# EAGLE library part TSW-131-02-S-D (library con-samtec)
THROUGH-HOLE .025" SQ POST HEADER Source: Samtec TSW.pdf
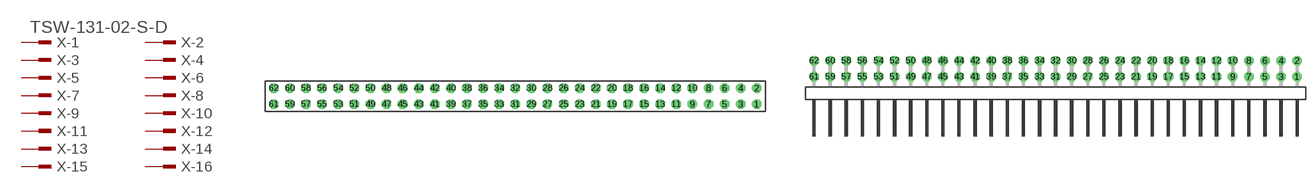
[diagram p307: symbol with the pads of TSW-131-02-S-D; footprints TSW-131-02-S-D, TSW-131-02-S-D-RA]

Designator prefix X; gates -1=MPINV -2=MPIN -3=MPIN -4=MPIN -5=MPIN -6=MPIN -7=MPIN -8=MPIN -9=MPIN -10=MPIN -11=MPIN -12=MPIN -13=MPIN -14=MPIN -15=MPIN -16=MPIN -17=MPIN -18=MPIN -19=MPIN -20=MPIN -21=MPIN -22=MPIN -23=MPIN -24=MPIN -25=MPIN -26=MPIN -27=MPIN -28=MPIN -29=MPIN -30=MPIN -31=MPIN -32=MPIN -33=MPIN -34=MPIN -35=MPIN -36=MPIN -37=MPIN -38=MPIN -39=MPIN -40=MPIN -41=MPIN -42=MPIN -43=MPIN -44=MPIN -45=MPIN -46=MPIN -47=MPIN -48=MPIN -49=MPIN -50=MPIN -51=MPIN -52=MPIN -53=MPIN -54=MPIN -55=MPIN -56=MPIN -57=MPIN -58=MPIN -59=MPIN -60=MPIN -61=MPIN -62=MPIN

## TSW-131-02-S-D (OC_FARNELL: unknown; OC_NEWARK: unknown)  [TSW-131-02-S-D]
1  -1:1  pas
2  -2:1  pas
3  -3:1  pas
4  -4:1  pas
5  -5:1  pas
6  -6:1  pas
7  -7:1  pas
8  -8:1  pas
9  -9:1  pas
10  -10:1  pas
11  -11:1  pas
12  -12:1  pas
13  -13:1  pas
14  -14:1  pas
15  -15:1  pas
16  -16:1  pas
17  -17:1  pas
18  -18:1  pas
19  -19:1  pas
20  -20:1  pas
21  -21:1  pas
22  -22:1  pas
23  -23:1  pas
24  -24:1  pas
25  -25:1  pas
26  -26:1  pas
27  -27:1  pas
28  -28:1  pas
29  -29:1  pas
30  -30:1  pas
31  -31:1  pas
32  -32:1  pas
33  -33:1  pas
34  -34:1  pas
35  -35:1  pas
36  -36:1  pas
37  -37:1  pas
38  -38:1  pas
39  -39:1  pas
40  -40:1  pas
41  -41:1  pas
42  -42:1  pas
43  -43:1  pas
44  -44:1  pas
45  -45:1  pas
46  -46:1  pas
47  -47:1  pas
48  -48:1  pas
49  -49:1  pas
50  -50:1  pas
51  -51:1  pas
52  -52:1  pas
53  -53:1  pas
54  -54:1  pas
55  -55:1  pas
56  -56:1  pas
57  -57:1  pas
58  -58:1  pas
59  -59:1  pas
60  -60:1  pas
61  -61:1  pas
62  -62:1  pas

## TSW-131-02-S-D-RA (OC_FARNELL: unknown; OC_NEWARK: unknown)  [TSW-131-02-S-D-RA]
Pads as for TSW-131-02-S-D

## Footprint TSW-131-02-S-D (pad centres in mm)
THROUGH-HOLE .025" SQ POST HEADER Source: Samtec TSW.pdf
drill 1 pad 1.5 octagon: 1 38.1,-1.27; 2 38.1,1.27; 3 35.56,-1.27; 4 35.56,1.27; 5 33.02,-1.27; 6 33.02,1.27; 7 30.48,-1.27; 8 30.48,1.27; 9 27.94,-1.27; 10 27.94,1.27; 11 25.4,-1.27; 12 25.4,1.27; 13 22.86,-1.27; 14 22.86,1.27; 15 20.32,-1.27; 16 20.32,1.27; 17 17.78,-1.27; 18 17.78,1.27; 19 15.24,-1.27; 20 15.24,1.27; 21 12.7,-1.27; 22 12.7,1.27; 23 10.16,-1.27; 24 10.16,1.27; 25 7.62,-1.27; 26 7.62,1.27; 27 5.08,-1.27; 28 5.08,1.27; 29 2.54,-1.27; 30 2.54,1.27; 31 0,-1.27; 32 0,1.27; 33 -2.54,-1.27; 34 -2.54,1.27; 35 -5.08,-1.27; 36 -5.08,1.27; 37 -7.62,-1.27; 38 -7.62,1.27; 39 -10.16,-1.27; 40 -10.16,1.27; 41 -12.7,-1.27; 42 -12.7,1.27; 43 -15.24,-1.27; 44 -15.24,1.27; 45 -17.78,-1.27; 46 -17.78,1.27; 47 -20.32,-1.27; 48 -20.32,1.27; 49 -22.86,-1.27; 50 -22.86,1.27; 51 -25.4,-1.27; 52 -25.4,1.27; 53 -27.94,-1.27; 54 -27.94,1.27; 55 -30.48,-1.27; 56 -30.48,1.27; 57 -33.02,-1.27; 58 -33.02,1.27; 59 -35.56,-1.27; 60 -35.56,1.27; 61 -38.1,-1.27; 62 -38.1,1.27

## Footprint TSW-131-02-S-D-RA (pad centres in mm)
THROUGH-HOLE .025" SQ POST HEADER Source: Samtec TSW.pdf
drill 1 pad 1.5 octagon: 1 38.1,1.524; 2 38.1,4.064; 3 35.56,1.524; 4 35.56,4.064; 5 33.02,1.524; 6 33.02,4.064; 7 30.48,1.524; 8 30.48,4.064; 9 27.94,1.524; 10 27.94,4.064; 11 25.4,1.524; 12 25.4,4.064; 13 22.86,1.524; 14 22.86,4.064; 15 20.32,1.524; 16 20.32,4.064; 17 17.78,1.524; 18 17.78,4.064; 19 15.24,1.524; 20 15.24,4.064; 21 12.7,1.524; 22 12.7,4.064; 23 10.16,1.524; 24 10.16,4.064; 25 7.62,1.524; 26 7.62,4.064; 27 5.08,1.524; 28 5.08,4.064; 29 2.54,1.524; 30 2.54,4.064; 31 0,1.524; 32 0,4.064; 33 -2.54,1.524; 34 -2.54,4.064; 35 -5.08,1.524; 36 -5.08,4.064; 37 -7.62,1.524; 38 -7.62,4.064; 39 -10.16,1.524; 40 -10.16,4.064; 41 -12.7,1.524; 42 -12.7,4.064; 43 -15.24,1.524; 44 -15.24,4.064; 45 -17.78,1.524; 46 -17.78,4.064; 47 -20.32,1.524; 48 -20.32,4.064; 49 -22.86,1.524; 50 -22.86,4.064; 51 -25.4,1.524; 52 -25.4,4.064; 53 -27.94,1.524; 54 -27.94,4.064; 55 -30.48,1.524; 56 -30.48,4.064; 57 -33.02,1.524; 58 -33.02,4.064; 59 -35.56,1.524; 60 -35.56,4.064; 61 -38.1,1.524; 62 -38.1,4.064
